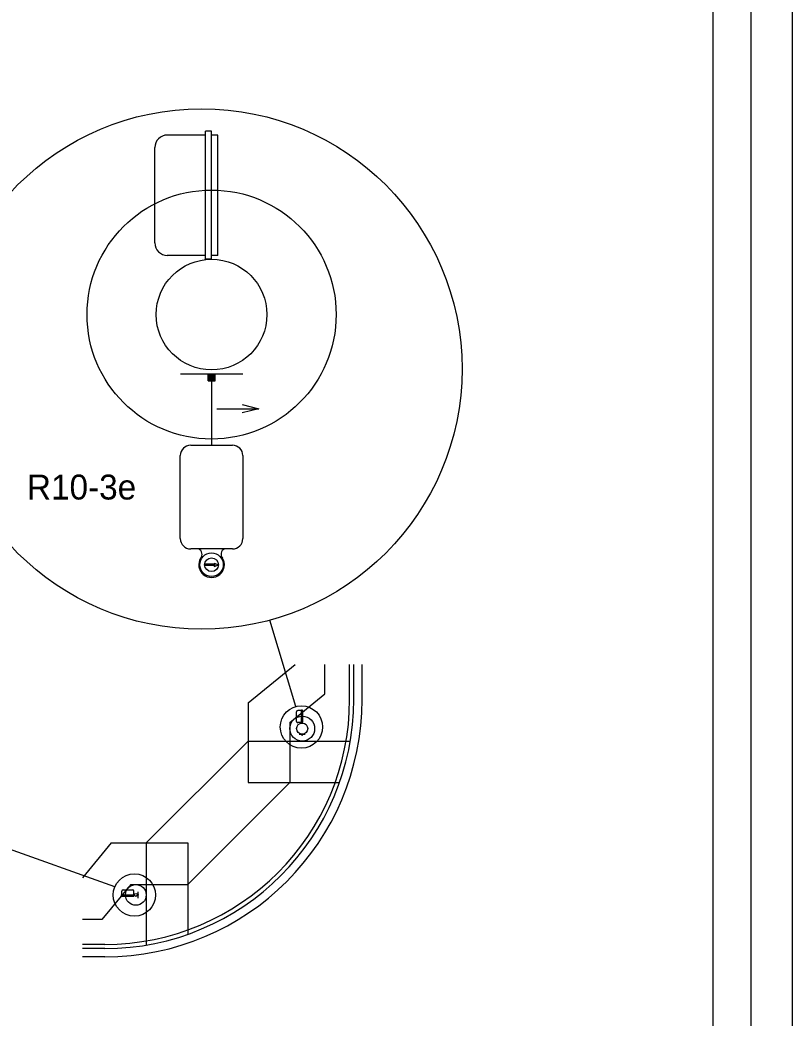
# Model space of a CAD drawing. Extents: x 1695551 to 1695718, y 544410 to 544516.
# Drawn here: x 1695694.69 to 1695717.93, y 544427.25 to 544457.31 of the extents above; entities that cross this region are included whole.
import ezdxf

# ---------------------------------------------------------------- set-up
doc = ezdxf.new("R2010")
doc.units = 0
for name, color, linetype in [('0_Plot Shape', 7, 'Continuous'), ('R_Border', 7, 'Continuous'), ('R_No Plot', 7, 'Continuous'), ('T_Drafting', 7, 'Continuous')]:
    doc.layers.add(name, color=color, linetype=linetype)

msp = doc.modelspace()

# ---------------------------------------------------------------- linework, layer by layer
at = {"layer": '0_Plot Shape'}
msp.add_lwpolyline([(1695551.694, 544515.386), (1695716.694, 544515.386), (1695716.694, 544410.386), (1695551.694, 544410.386)], close=True, dxfattribs=at)
at = {"layer": 'R_Border'}
msp.add_line((1695715.559, 544411.521), (1695715.559, 544514.251), dxfattribs=at)
at = {"layer": 'R_No Plot'}
msp.add_lwpolyline([(1695551.265, 544516.198), (1695717.935, 544516.198), (1695717.935, 544409.529), (1695551.265, 544409.529)], close=True, dxfattribs=at)
at = {"layer": 'T_Drafting'}
for p, q in [((1695700.27, 544453.846), (1695699.124, 544453.846)), ((1695700.27, 544450.106), (1695700.27, 544453.961)), ((1695700.457, 544453.961), (1695700.27, 544453.961)), ((1695700.457, 544450.106), (1695700.457, 544453.961)), ((1695700.645, 544453.846), (1695700.457, 544453.846)), ((1695700.645, 544450.221), (1695700.645, 544453.846)), ((1695698.749, 544450.596), (1695698.749, 544453.471)), ((1695700.27, 544450.221), (1695699.124, 544450.221)), ((1695700.457, 544450.106), (1695700.27, 544450.106)), ((1695700.645, 544450.221), (1695700.457, 544450.221)), ((1695701.395, 544446.648), (1695699.52, 544446.648)), ((1695700.353, 544446.44), (1695700.353, 544446.648)), ((1695700.353, 544446.441), (1695700.56, 544446.648)), ((1695700.353, 544446.445), (1695700.556, 544446.648)), ((1695700.353, 544446.448), (1695700.553, 544446.648)), ((1695700.353, 544446.452), (1695700.549, 544446.648)), ((1695700.353, 544446.455), (1695700.546, 544446.648)), ((1695700.353, 544446.459), (1695700.542, 544446.648)), ((1695700.353, 544446.462), (1695700.539, 544446.648)), ((1695700.353, 544446.466), (1695700.535, 544446.648)), ((1695700.353, 544446.469), (1695700.532, 544446.648)), ((1695700.353, 544446.473), (1695700.528, 544446.648)), ((1695700.353, 544446.477), (1695700.524, 544446.648)), ((1695700.353, 544446.48), (1695700.521, 544446.648)), ((1695700.353, 544446.484), (1695700.517, 544446.648)), ((1695700.353, 544446.487), (1695700.514, 544446.648)), ((1695700.353, 544446.491), (1695700.51, 544446.648)), ((1695700.353, 544446.494), (1695700.507, 544446.648)), ((1695700.353, 544446.498), (1695700.503, 544446.648)), ((1695700.353, 544446.501), (1695700.5, 544446.648)), ((1695700.353, 544446.505), (1695700.496, 544446.648)), ((1695700.353, 544446.508), (1695700.493, 544446.648)), ((1695700.353, 544446.512), (1695700.489, 544446.648)), ((1695700.353, 544446.515), (1695700.486, 544446.648)), ((1695700.353, 544446.519), (1695700.482, 544446.648)), ((1695700.353, 544446.523), (1695700.478, 544446.648)), ((1695700.353, 544446.526), (1695700.475, 544446.648)), ((1695700.353, 544446.53), (1695700.471, 544446.648)), ((1695700.353, 544446.533), (1695700.468, 544446.648)), ((1695700.353, 544446.537), (1695700.464, 544446.648)), ((1695700.353, 544446.54), (1695700.461, 544446.648)), ((1695700.353, 544446.544), (1695700.457, 544446.648)), ((1695700.353, 544446.547), (1695700.454, 544446.648)), ((1695700.353, 544446.551), (1695700.45, 544446.648)), ((1695700.353, 544446.554), (1695700.447, 544446.648)), ((1695700.353, 544446.558), (1695700.443, 544446.648)), ((1695700.353, 544446.561), (1695700.44, 544446.648)), ((1695700.353, 544446.565), (1695700.436, 544446.648)), ((1695700.353, 544446.568), (1695700.433, 544446.648)), ((1695700.353, 544446.572), (1695700.429, 544446.648)), ((1695700.353, 544446.576), (1695700.425, 544446.648)), ((1695700.353, 544446.579), (1695700.422, 544446.648)), ((1695700.353, 544446.583), (1695700.418, 544446.648)), ((1695700.353, 544446.586), (1695700.415, 544446.648)), ((1695700.353, 544446.59), (1695700.411, 544446.648)), ((1695700.353, 544446.593), (1695700.408, 544446.648)), ((1695700.353, 544446.597), (1695700.404, 544446.648)), ((1695700.353, 544446.6), (1695700.401, 544446.648)), ((1695700.353, 544446.604), (1695700.397, 544446.648)), ((1695700.353, 544446.607), (1695700.394, 544446.648)), ((1695700.353, 544446.611), (1695700.39, 544446.648)), ((1695700.353, 544446.614), (1695700.387, 544446.648)), ((1695700.353, 544446.618), (1695700.383, 544446.648)), ((1695700.353, 544446.622), (1695700.379, 544446.648)), ((1695700.353, 544446.625), (1695700.376, 544446.648)), ((1695700.353, 544446.629), (1695700.372, 544446.648)), ((1695700.353, 544446.632), (1695700.369, 544446.648)), ((1695700.353, 544446.636), (1695700.365, 544446.648)), ((1695700.353, 544446.639), (1695700.362, 544446.648)), ((1695700.353, 544446.643), (1695700.358, 544446.648)), ((1695700.353, 544446.646), (1695700.355, 544446.648)), ((1695700.355, 544446.44), (1695700.561, 544446.646)), ((1695700.359, 544446.44), (1695700.561, 544446.642)), ((1695700.362, 544446.44), (1695700.561, 544446.639)), ((1695700.366, 544446.44), (1695700.561, 544446.635)), ((1695700.369, 544446.44), (1695700.561, 544446.632)), ((1695700.373, 544446.44), (1695700.561, 544446.628)), ((1695700.376, 544446.44), (1695700.561, 544446.625)), ((1695700.38, 544446.44), (1695700.561, 544446.621)), ((1695700.383, 544446.44), (1695700.561, 544446.618)), ((1695700.387, 544446.44), (1695700.561, 544446.614)), ((1695700.39, 544446.44), (1695700.561, 544446.611)), ((1695700.394, 544446.44), (1695700.561, 544446.607)), ((1695700.397, 544446.44), (1695700.561, 544446.604)), ((1695700.401, 544446.44), (1695700.561, 544446.6)), ((1695700.404, 544446.44), (1695700.561, 544446.597)), ((1695700.408, 544446.44), (1695700.561, 544446.593)), ((1695700.412, 544446.44), (1695700.561, 544446.589)), ((1695700.415, 544446.44), (1695700.561, 544446.586)), ((1695700.419, 544446.44), (1695700.561, 544446.582)), ((1695700.422, 544446.44), (1695700.561, 544446.579)), ((1695700.426, 544446.44), (1695700.561, 544446.575)), ((1695700.429, 544446.44), (1695700.561, 544446.572)), ((1695700.433, 544446.44), (1695700.561, 544446.568)), ((1695700.436, 544446.44), (1695700.561, 544446.565)), ((1695700.44, 544446.44), (1695700.561, 544446.561)), ((1695700.443, 544446.44), (1695700.561, 544446.558)), ((1695700.447, 544446.44), (1695700.561, 544446.554)), ((1695700.45, 544446.44), (1695700.561, 544446.551)), ((1695700.454, 544446.44), (1695700.561, 544446.547)), ((1695700.458, 544446.44), (1695700.561, 544446.543)), ((1695700.461, 544446.44), (1695700.561, 544446.54)), ((1695700.465, 544446.44), (1695700.561, 544446.536)), ((1695700.468, 544446.44), (1695700.561, 544446.533)), ((1695700.472, 544446.44), (1695700.561, 544446.529)), ((1695700.475, 544446.44), (1695700.561, 544446.526)), ((1695700.479, 544446.44), (1695700.561, 544446.522)), ((1695700.482, 544446.44), (1695700.561, 544446.519)), ((1695700.486, 544446.44), (1695700.561, 544446.515)), ((1695700.489, 544446.44), (1695700.561, 544446.512)), ((1695700.493, 544446.44), (1695700.561, 544446.508)), ((1695700.496, 544446.44), (1695700.561, 544446.505)), ((1695700.5, 544446.44), (1695700.561, 544446.501)), ((1695700.503, 544446.44), (1695700.561, 544446.498)), ((1695700.507, 544446.44), (1695700.561, 544446.494)), ((1695700.511, 544446.44), (1695700.561, 544446.49)), ((1695700.514, 544446.44), (1695700.561, 544446.487)), ((1695700.518, 544446.44), (1695700.561, 544446.483)), ((1695700.521, 544446.44), (1695700.561, 544446.48)), ((1695700.525, 544446.44), (1695700.561, 544446.476)), ((1695700.528, 544446.44), (1695700.561, 544446.473)), ((1695700.532, 544446.44), (1695700.561, 544446.469)), ((1695700.535, 544446.44), (1695700.561, 544446.466)), ((1695700.539, 544446.44), (1695700.561, 544446.462)), ((1695700.542, 544446.44), (1695700.561, 544446.459)), ((1695700.561, 544446.44), (1695700.561, 544446.648)), ((1695700.353, 544446.44), (1695700.561, 544446.44)), ((1695700.457, 544446.44), (1695700.457, 544444.506)), ((1695700.546, 544446.44), (1695700.561, 544446.455)), ((1695700.549, 544446.44), (1695700.561, 544446.452)), ((1695700.553, 544446.44), (1695700.561, 544446.448)), ((1695700.557, 544446.44), (1695700.561, 544446.444)), ((1695700.56, 544446.44), (1695700.561, 544446.441)), ((1695700.618, 544445.606), (1695701.876, 544445.606)), ((1695699.828, 544444.506), (1695701.086, 544444.506)), ((1695699.516, 544441.693), (1695699.516, 544444.193)), ((1695701.399, 544444.193), (1695701.399, 544441.693)), ((1695701.086, 544441.381), (1695699.828, 544441.381)), ((1695700.25, 544440.924), (1695700.25, 544440.887)), ((1695700.564, 544440.924), (1695700.25, 544440.924)), ((1695700.564, 544440.887), (1695700.25, 544440.887)), ((1695700.539, 544440.956), (1695700.665, 544440.906)), ((1695700.564, 544440.924), (1695700.539, 544440.956)), ((1695700.539, 544440.856), (1695700.665, 544440.906)), ((1695700.539, 544440.856), (1695700.564, 544440.887)), ((1695702.994, 544436.635), (1695702.209, 544439.236)), ((1695701.561, 544436.745), (1695702.97, 544437.904)), ((1695703.864, 544437.021), (1695703.864, 544437.904)), ((1695704.614, 544436.847), (1695704.614, 544437.904)), ((1695704.739, 544436.847), (1695704.739, 544437.904)), ((1695704.989, 544436.847), (1695704.989, 544437.904)), ((1695702.811, 544436.155), (1695703.864, 544437.021)), ((1695701.561, 544436.745), (1695701.561, 544434.347)), ((1695703.015, 544436.187), (1695703.015, 544436.475)), ((1695703.167, 544436.512), (1695703.052, 544436.512)), ((1695703.167, 544436.138), (1695703.167, 544436.524)), ((1695703.186, 544436.524), (1695703.167, 544436.524)), ((1695703.186, 544436.138), (1695703.186, 544436.524)), ((1695703.204, 544436.512), (1695703.186, 544436.512)), ((1695703.204, 544436.15), (1695703.204, 544436.512)), ((1695702.811, 544436.155), (1695702.811, 544434.347)), ((1695703.167, 544436.15), (1695703.052, 544436.15)), ((1695703.186, 544436.138), (1695703.167, 544436.138)), ((1695703.204, 544436.15), (1695703.186, 544436.15)), ((1695703.279, 544435.792), (1695703.092, 544435.792)), ((1695703.175, 544435.772), (1695703.175, 544435.792)), ((1695703.175, 544435.772), (1695703.196, 544435.792)), ((1695703.175, 544435.772), (1695703.196, 544435.792)), ((1695703.175, 544435.772), (1695703.195, 544435.792)), ((1695703.175, 544435.772), (1695703.195, 544435.792)), ((1695703.175, 544435.773), (1695703.195, 544435.792)), ((1695703.175, 544435.773), (1695703.194, 544435.792)), ((1695703.175, 544435.773), (1695703.194, 544435.792)), ((1695703.175, 544435.774), (1695703.194, 544435.792)), ((1695703.175, 544435.774), (1695703.193, 544435.792)), ((1695703.175, 544435.775), (1695703.193, 544435.792)), ((1695703.175, 544435.775), (1695703.193, 544435.792)), ((1695703.175, 544435.775), (1695703.192, 544435.792)), ((1695703.175, 544435.776), (1695703.192, 544435.792)), ((1695703.175, 544435.776), (1695703.192, 544435.792)), ((1695703.175, 544435.776), (1695703.191, 544435.792)), ((1695703.175, 544435.777), (1695703.191, 544435.792)), ((1695703.175, 544435.777), (1695703.191, 544435.792)), ((1695703.175, 544435.777), (1695703.19, 544435.792)), ((1695703.175, 544435.778), (1695703.19, 544435.792)), ((1695703.175, 544435.778), (1695703.189, 544435.792)), ((1695703.175, 544435.778), (1695703.189, 544435.792)), ((1695703.175, 544435.779), (1695703.189, 544435.792)), ((1695703.175, 544435.779), (1695703.188, 544435.792)), ((1695703.175, 544435.779), (1695703.188, 544435.792)), ((1695703.175, 544435.78), (1695703.188, 544435.792)), ((1695703.175, 544435.78), (1695703.187, 544435.792)), ((1695703.175, 544435.781), (1695703.187, 544435.792)), ((1695703.175, 544435.781), (1695703.187, 544435.792)), ((1695703.175, 544435.781), (1695703.186, 544435.792)), ((1695703.175, 544435.782), (1695703.186, 544435.792)), ((1695703.175, 544435.782), (1695703.186, 544435.792)), ((1695703.175, 544435.782), (1695703.185, 544435.792)), ((1695703.175, 544435.783), (1695703.185, 544435.792)), ((1695703.175, 544435.783), (1695703.185, 544435.792)), ((1695703.175, 544435.783), (1695703.184, 544435.792)), ((1695703.175, 544435.784), (1695703.184, 544435.792)), ((1695703.175, 544435.784), (1695703.183, 544435.792)), ((1695703.175, 544435.784), (1695703.183, 544435.792)), ((1695703.175, 544435.785), (1695703.183, 544435.792)), ((1695703.175, 544435.785), (1695703.182, 544435.792)), ((1695703.175, 544435.786), (1695703.182, 544435.792)), ((1695703.175, 544435.786), (1695703.182, 544435.792)), ((1695703.175, 544435.786), (1695703.181, 544435.792)), ((1695703.175, 544435.787), (1695703.181, 544435.792)), ((1695703.175, 544435.787), (1695703.181, 544435.792)), ((1695703.175, 544435.787), (1695703.18, 544435.792)), ((1695703.175, 544435.788), (1695703.18, 544435.792)), ((1695703.175, 544435.788), (1695703.18, 544435.792)), ((1695703.175, 544435.788), (1695703.179, 544435.792)), ((1695703.175, 544435.789), (1695703.179, 544435.792)), ((1695703.175, 544435.789), (1695703.178, 544435.792)), ((1695703.175, 544435.789), (1695703.178, 544435.792)), ((1695703.175, 544435.79), (1695703.178, 544435.792)), ((1695703.175, 544435.79), (1695703.177, 544435.792)), ((1695703.175, 544435.79), (1695703.177, 544435.792)), ((1695703.175, 544435.791), (1695703.177, 544435.792)), ((1695703.175, 544435.791), (1695703.176, 544435.792)), ((1695703.175, 544435.792), (1695703.176, 544435.792)), ((1695703.175, 544435.792), (1695703.176, 544435.792)), ((1695703.175, 544435.792), (1695703.175, 544435.792)), ((1695703.175, 544435.772), (1695703.196, 544435.772)), ((1695703.176, 544435.772), (1695703.196, 544435.792)), ((1695703.176, 544435.772), (1695703.196, 544435.791)), ((1695703.176, 544435.772), (1695703.196, 544435.791)), ((1695703.177, 544435.772), (1695703.196, 544435.791)), ((1695703.177, 544435.772), (1695703.196, 544435.79)), ((1695703.177, 544435.772), (1695703.196, 544435.79)), ((1695703.178, 544435.772), (1695703.196, 544435.79)), ((1695703.178, 544435.772), (1695703.196, 544435.789)), ((1695703.179, 544435.772), (1695703.196, 544435.789)), ((1695703.179, 544435.772), (1695703.196, 544435.789)), ((1695703.179, 544435.772), (1695703.196, 544435.788)), ((1695703.18, 544435.772), (1695703.196, 544435.788)), ((1695703.18, 544435.772), (1695703.196, 544435.788)), ((1695703.18, 544435.772), (1695703.196, 544435.787)), ((1695703.181, 544435.772), (1695703.196, 544435.787)), ((1695703.181, 544435.772), (1695703.196, 544435.787)), ((1695703.181, 544435.772), (1695703.196, 544435.786)), ((1695703.182, 544435.772), (1695703.196, 544435.786)), ((1695703.182, 544435.772), (1695703.196, 544435.785)), ((1695703.182, 544435.772), (1695703.196, 544435.785)), ((1695703.183, 544435.772), (1695703.196, 544435.785)), ((1695703.183, 544435.772), (1695703.196, 544435.784)), ((1695703.183, 544435.772), (1695703.196, 544435.784)), ((1695703.184, 544435.772), (1695703.196, 544435.784)), ((1695703.184, 544435.772), (1695703.196, 544435.783)), ((1695703.185, 544435.772), (1695703.196, 544435.783)), ((1695703.185, 544435.772), (1695703.196, 544435.783)), ((1695703.185, 544435.772), (1695703.196, 544435.782)), ((1695703.186, 544435.772), (1695703.196, 544435.782)), ((1695703.186, 544435.772), (1695703.196, 544435.782)), ((1695703.186, 544435.772), (1695703.196, 544435.781)), ((1695703.187, 544435.772), (1695703.196, 544435.781)), ((1695703.187, 544435.772), (1695703.196, 544435.781)), ((1695703.187, 544435.772), (1695703.196, 544435.78)), ((1695703.188, 544435.772), (1695703.196, 544435.78)), ((1695703.188, 544435.772), (1695703.196, 544435.779)), ((1695703.188, 544435.772), (1695703.196, 544435.779)), ((1695703.189, 544435.772), (1695703.196, 544435.779)), ((1695703.189, 544435.772), (1695703.196, 544435.778)), ((1695703.189, 544435.772), (1695703.196, 544435.778)), ((1695703.19, 544435.772), (1695703.196, 544435.778)), ((1695703.19, 544435.772), (1695703.196, 544435.777)), ((1695703.191, 544435.772), (1695703.196, 544435.777)), ((1695703.191, 544435.772), (1695703.196, 544435.777)), ((1695703.191, 544435.772), (1695703.196, 544435.776)), ((1695703.192, 544435.772), (1695703.196, 544435.776)), ((1695703.192, 544435.772), (1695703.196, 544435.776)), ((1695703.192, 544435.772), (1695703.196, 544435.775)), ((1695703.193, 544435.772), (1695703.196, 544435.775)), ((1695703.193, 544435.772), (1695703.196, 544435.775)), ((1695703.193, 544435.772), (1695703.196, 544435.774)), ((1695703.194, 544435.772), (1695703.196, 544435.774)), ((1695703.194, 544435.772), (1695703.196, 544435.773)), ((1695703.194, 544435.772), (1695703.196, 544435.773)), ((1695703.195, 544435.772), (1695703.196, 544435.773)), ((1695703.195, 544435.772), (1695703.196, 544435.772)), ((1695703.195, 544435.772), (1695703.196, 544435.772)), ((1695703.196, 544435.772), (1695703.196, 544435.792)), ((1695703.196, 544435.772), (1695703.196, 544435.772)), ((1695701.561, 544435.597), (1695698.489, 544432.526)), ((1695701.561, 544435.597), (1695704.635, 544435.597)), ((1695702.811, 544434.347), (1695699.739, 544431.276)), ((1695701.561, 544434.347), (1695704.311, 544434.347)), ((1695697.544, 544431.204), (1695694.052, 544432.449)), ((1695697.433, 544432.526), (1695696.566, 544431.472)), ((1695697.433, 544432.526), (1695699.739, 544432.526)), ((1695698.489, 544432.526), (1695698.489, 544429.451)), ((1695699.739, 544432.526), (1695699.739, 544429.776)), ((1695698.023, 544431.276), (1695697.156, 544430.222)), ((1695698.023, 544431.276), (1695699.739, 544431.276)), ((1695697.745, 544430.963), (1695698.13, 544430.963)), ((1695697.745, 544430.944), (1695697.745, 544430.963)), ((1695697.745, 544430.944), (1695698.13, 544430.944)), ((1695697.756, 544430.963), (1695697.756, 544431.078)), ((1695697.756, 544430.926), (1695697.756, 544430.944)), ((1695697.756, 544430.926), (1695698.119, 544430.926)), ((1695697.794, 544431.115), (1695698.081, 544431.115)), ((1695698.119, 544430.963), (1695698.119, 544431.078)), ((1695698.119, 544430.926), (1695698.119, 544430.944)), ((1695698.13, 544430.944), (1695698.13, 544430.963)), ((1695698.236, 544431.057), (1695698.236, 544430.869)), ((1695698.257, 544430.973), (1695698.236, 544430.973)), ((1695698.236, 544430.953), (1695698.257, 544430.973)), ((1695698.236, 544430.953), (1695698.257, 544430.973)), ((1695698.236, 544430.953), (1695698.256, 544430.973)), ((1695698.236, 544430.954), (1695698.256, 544430.973)), ((1695698.236, 544430.954), (1695698.256, 544430.973)), ((1695698.236, 544430.954), (1695698.255, 544430.973)), ((1695698.236, 544430.955), (1695698.255, 544430.973)), ((1695698.236, 544430.955), (1695698.255, 544430.973)), ((1695698.236, 544430.955), (1695698.254, 544430.973)), ((1695698.236, 544430.956), (1695698.254, 544430.973)), ((1695698.236, 544430.956), (1695698.254, 544430.973)), ((1695698.236, 544430.957), (1695698.253, 544430.973)), ((1695698.236, 544430.957), (1695698.253, 544430.973)), ((1695698.236, 544430.957), (1695698.253, 544430.973)), ((1695698.236, 544430.958), (1695698.252, 544430.973)), ((1695698.236, 544430.958), (1695698.252, 544430.973)), ((1695698.236, 544430.958), (1695698.251, 544430.973)), ((1695698.236, 544430.959), (1695698.251, 544430.973)), ((1695698.236, 544430.959), (1695698.251, 544430.973)), ((1695698.236, 544430.959), (1695698.25, 544430.973)), ((1695698.236, 544430.96), (1695698.25, 544430.973)), ((1695698.236, 544430.96), (1695698.25, 544430.973)), ((1695698.236, 544430.96), (1695698.249, 544430.973)), ((1695698.236, 544430.961), (1695698.249, 544430.973)), ((1695698.236, 544430.961), (1695698.249, 544430.973)), ((1695698.236, 544430.961), (1695698.248, 544430.973)), ((1695698.236, 544430.962), (1695698.248, 544430.973)), ((1695698.236, 544430.962), (1695698.248, 544430.973)), ((1695698.236, 544430.963), (1695698.247, 544430.973)), ((1695698.236, 544430.963), (1695698.247, 544430.973)), ((1695698.236, 544430.963), (1695698.247, 544430.973)), ((1695698.236, 544430.964), (1695698.246, 544430.973)), ((1695698.236, 544430.964), (1695698.246, 544430.973)), ((1695698.236, 544430.964), (1695698.245, 544430.973)), ((1695698.236, 544430.965), (1695698.245, 544430.973)), ((1695698.236, 544430.965), (1695698.245, 544430.973)), ((1695698.236, 544430.965), (1695698.244, 544430.973)), ((1695698.236, 544430.966), (1695698.244, 544430.973)), ((1695698.236, 544430.966), (1695698.244, 544430.973)), ((1695698.236, 544430.966), (1695698.243, 544430.973)), ((1695698.236, 544430.967), (1695698.243, 544430.973)), ((1695698.236, 544430.967), (1695698.243, 544430.973)), ((1695698.236, 544430.968), (1695698.242, 544430.973)), ((1695698.236, 544430.968), (1695698.242, 544430.973)), ((1695698.236, 544430.968), (1695698.242, 544430.973)), ((1695698.236, 544430.969), (1695698.241, 544430.973)), ((1695698.236, 544430.969), (1695698.241, 544430.973)), ((1695698.236, 544430.969), (1695698.241, 544430.973)), ((1695698.236, 544430.97), (1695698.24, 544430.973)), ((1695698.236, 544430.97), (1695698.24, 544430.973)), ((1695698.236, 544430.97), (1695698.239, 544430.973)), ((1695698.236, 544430.971), (1695698.239, 544430.973)), ((1695698.236, 544430.971), (1695698.239, 544430.973)), ((1695698.236, 544430.971), (1695698.238, 544430.973)), ((1695698.236, 544430.972), (1695698.238, 544430.973)), ((1695698.236, 544430.972), (1695698.238, 544430.973)), ((1695698.236, 544430.972), (1695698.237, 544430.973)), ((1695698.236, 544430.973), (1695698.237, 544430.973)), ((1695698.236, 544430.973), (1695698.237, 544430.973)), ((1695698.257, 544430.953), (1695698.236, 544430.953)), ((1695698.237, 544430.953), (1695698.257, 544430.973)), ((1695698.237, 544430.953), (1695698.257, 544430.973)), ((1695698.237, 544430.953), (1695698.257, 544430.972)), ((1695698.238, 544430.953), (1695698.257, 544430.972)), ((1695698.238, 544430.953), (1695698.257, 544430.972)), ((1695698.238, 544430.953), (1695698.257, 544430.971)), ((1695698.239, 544430.953), (1695698.257, 544430.971)), ((1695698.239, 544430.953), (1695698.257, 544430.971)), ((1695698.239, 544430.953), (1695698.257, 544430.97)), ((1695698.24, 544430.953), (1695698.257, 544430.97)), ((1695698.24, 544430.953), (1695698.257, 544430.97)), ((1695698.241, 544430.953), (1695698.257, 544430.969)), ((1695698.241, 544430.953), (1695698.257, 544430.969)), ((1695698.241, 544430.953), (1695698.257, 544430.969)), ((1695698.242, 544430.953), (1695698.257, 544430.968)), ((1695698.242, 544430.953), (1695698.257, 544430.968)), ((1695698.242, 544430.953), (1695698.257, 544430.967)), ((1695698.243, 544430.953), (1695698.257, 544430.967)), ((1695698.243, 544430.953), (1695698.257, 544430.967)), ((1695698.243, 544430.953), (1695698.257, 544430.966)), ((1695698.244, 544430.953), (1695698.257, 544430.966)), ((1695698.244, 544430.953), (1695698.257, 544430.966)), ((1695698.244, 544430.953), (1695698.257, 544430.965)), ((1695698.245, 544430.953), (1695698.257, 544430.965)), ((1695698.245, 544430.953), (1695698.257, 544430.965)), ((1695698.245, 544430.953), (1695698.257, 544430.964)), ((1695698.246, 544430.953), (1695698.257, 544430.964)), ((1695698.246, 544430.953), (1695698.257, 544430.964)), ((1695698.247, 544430.953), (1695698.257, 544430.963)), ((1695698.247, 544430.953), (1695698.257, 544430.963)), ((1695698.247, 544430.953), (1695698.257, 544430.963)), ((1695698.248, 544430.953), (1695698.257, 544430.962)), ((1695698.248, 544430.953), (1695698.257, 544430.962)), ((1695698.248, 544430.953), (1695698.257, 544430.961)), ((1695698.249, 544430.953), (1695698.257, 544430.961)), ((1695698.249, 544430.953), (1695698.257, 544430.961)), ((1695698.249, 544430.953), (1695698.257, 544430.96)), ((1695698.25, 544430.953), (1695698.257, 544430.96)), ((1695698.25, 544430.953), (1695698.257, 544430.96)), ((1695698.25, 544430.953), (1695698.257, 544430.959)), ((1695698.251, 544430.953), (1695698.257, 544430.959)), ((1695698.251, 544430.953), (1695698.257, 544430.959)), ((1695698.251, 544430.953), (1695698.257, 544430.958)), ((1695698.252, 544430.953), (1695698.257, 544430.958)), ((1695698.252, 544430.953), (1695698.257, 544430.958)), ((1695698.253, 544430.953), (1695698.257, 544430.957)), ((1695698.253, 544430.953), (1695698.257, 544430.957)), ((1695698.253, 544430.953), (1695698.257, 544430.957)), ((1695698.254, 544430.953), (1695698.257, 544430.956)), ((1695698.254, 544430.953), (1695698.257, 544430.956)), ((1695698.254, 544430.953), (1695698.257, 544430.955)), ((1695698.255, 544430.953), (1695698.257, 544430.955)), ((1695698.255, 544430.953), (1695698.257, 544430.955)), ((1695698.255, 544430.953), (1695698.257, 544430.954)), ((1695698.256, 544430.953), (1695698.257, 544430.954)), ((1695698.256, 544430.953), (1695698.257, 544430.954)), ((1695698.256, 544430.953), (1695698.257, 544430.953)), ((1695698.257, 544430.953), (1695698.257, 544430.973)), ((1695698.257, 544430.953), (1695698.257, 544430.953)), ((1695698.257, 544430.953), (1695698.257, 544430.953)), ((1695697.156, 544430.222), (1695696.566, 544430.222)), ((1695697.239, 544429.472), (1695696.566, 544429.472)), ((1695697.239, 544429.347), (1695696.566, 544429.347)), ((1695697.239, 544429.097), (1695696.566, 544429.097))]:
    msp.add_line(p, q, dxfattribs=at)
msp.add_lwpolyline([(1695701.376, 544445.731), (1695701.876, 544445.606), (1695701.376, 544445.481)], dxfattribs=at)
for centre, radius in [((1695700.16, 544446.801), 7.838), ((1695700.457, 544448.44), 3.75), ((1695700.457, 544448.44), 1.667), ((1695700.457, 544440.906), 0.354), ((1695700.457, 544440.906), 0.208), ((1695703.164, 544436.02), 0.638), ((1695703.186, 544435.972), 0.375), ((1695703.186, 544435.972), 0.167), ((1695698.134, 544430.96), 0.638), ((1695698.177, 544430.963), 0.312), ((1695698.177, 544430.963), 0.0469)]:
    msp.add_circle(centre, radius, dxfattribs=at)
for centre, radius, start, end in [((1695699.124, 544453.471), 0.375, 90, 180), ((1695699.124, 544450.596), 0.375, 180, 270), ((1695699.828, 544444.193), 0.312, 90, 180), ((1695701.086, 544444.193), 0.312, 0, 90), ((1695699.828, 544441.693), 0.312, 180, 270), ((1695701.086, 544441.693), 0.312, 270, 0), ((1695699.997, 544441.222), 0.175, 318.1972, 64.8044), ((1695700.917, 544441.222), 0.175, 115.1956, 221.8028), ((1695700.457, 544440.906), 0.385, 148.7402, 227.4934), ((1695700.457, 544440.906), 0.385, 148.7402, 31.2598), ((1695700.457, 544440.906), 0.385, 312.5066, 31.2598), ((1695697.239, 544436.847), 7.5, 270, 0), ((1695697.239, 544436.847), 7.75, 270, 0), ((1695697.239, 544436.847), 7.375, 270, 0), ((1695703.052, 544436.475), 0.0375, 90, 180), ((1695703.052, 544436.187), 0.0375, 180, 270), ((1695697.794, 544431.078), 0.0375, 90, 180), ((1695698.081, 544431.078), 0.0375, 360, 90)]:
    msp.add_arc(centre, radius, start, end, dxfattribs=at)

# ---------------------------------------------------------------- texts
msp.add_text('R10-3e', height=0.75, dxfattribs=at).set_placement((1695694.898, 544442.87))

doc.saveas('drawing.dxf')
